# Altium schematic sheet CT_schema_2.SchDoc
size 309 x 321 mm
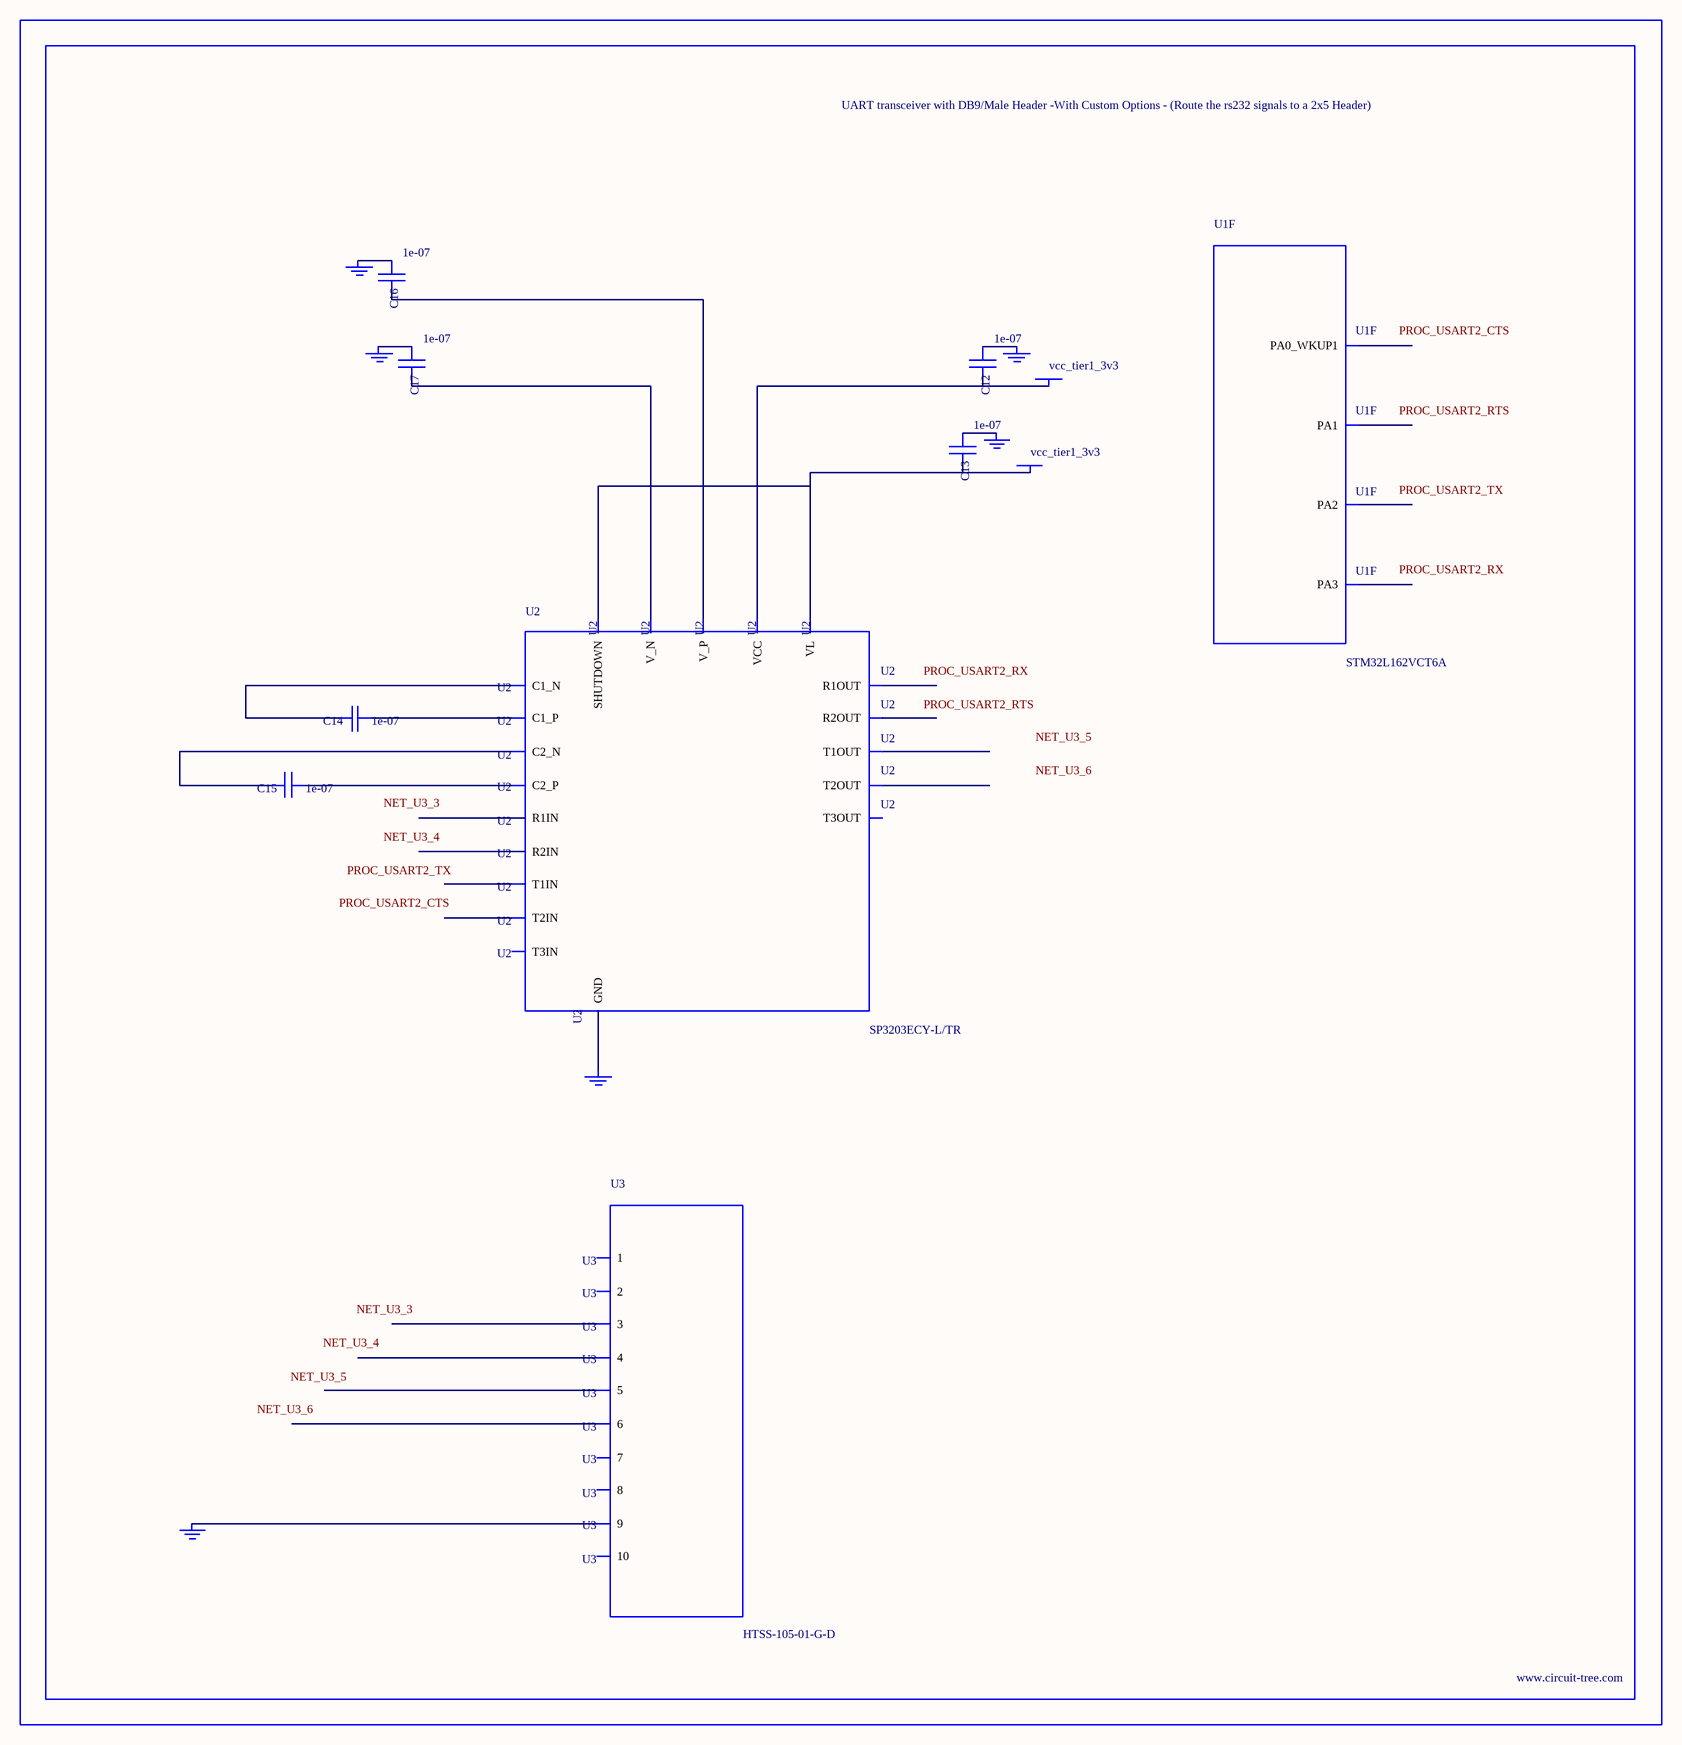
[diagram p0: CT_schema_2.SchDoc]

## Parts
BORDER1  (no value)
C12  1e-07  [C0402]
C13  1e-07  [C0402]
C14  1e-07  [C0402]
C15  1e-07  [C0402]
C16  1e-07  [C0402]
C17  1e-07  [C0402]
GND_INSTANCE_1_0  (no value)
GND_INSTANCE_1_1  (no value)
GND_INSTANCE_1_2  (no value)
GND_INSTANCE_1_3  (no value)
GND_INSTANCE_1_4  (no value)
GND_INSTANCE_1_5  (no value)
POWER_INSTANCE_1_0  vcc_tier1_3v3
POWER_INSTANCE_1_1  vcc_tier1_3v3
U1  STM32L162VCT6A  [LQFP100]  (part F of 9)
U2  SP3203ECY-L/TR  [TSSOP20-I]
U3  HTSS-105-01-G-D  [HTSS-105-01-G-D]

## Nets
NetC12_1: C12.1 GND_INSTANCE_1_3.0(GND)
NetC12_2: C12.2 POWER_INSTANCE_1_1.0(PWR) U2.19(VCC)
NetC13_1: C13.1 GND_INSTANCE_1_2.0(GND)
NetC13_2: C13.2 POWER_INSTANCE_1_0.0(PWR) U2.12(VL) U2.20(SHUTDOWN)
NetC14_1: C14.1 U2.1(C1_P)
NetC14_2: C14.2 U2.3(C1_N)
NetC15_1: C15.1 U2.4(C2_P)
NetC15_2: C15.2 U2.5(C2_N)
NetC16_1: C16.1 GND_INSTANCE_1_0.0(GND)
NetC16_2: C16.2 U2.2(V_P)
NetC17_1: C17.1 GND_INSTANCE_1_1.0(GND)
NetC17_2: C17.2 U2.6(V_N)
NetGND_INSTANCE_1_4_0: GND_INSTANCE_1_4.0(GND) U2.18(GND)
NetGND_INSTANCE_1_5_0: GND_INSTANCE_1_5.0(GND) U3.9

Not connected (* = marked no-connect by the designer): U1 23(PA0_WKUP1) 24(PA1) 25(PA2) 26(PA3); U2 7(T1IN) 8(T2IN) 9(T3IN) 10(R2OUT) 11(R1OUT) 13(R2IN) 14(R1IN) 15(T3OUT) 16(T2OUT) 17(T1OUT); U3 1 2 3 4 5 6 7 8 10

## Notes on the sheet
- Labels drawn without touching a wire or pin: NET_U3_3, NET_U3_4, NET_U3_5, NET_U3_6, PROC_USART2_CTS, PROC_USART2_RTS, PROC_USART2_RX, PROC_USART2_TX

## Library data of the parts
BORDER1 = BORDER_PAGE1
C12-C17 = C0402C104K3RACTU
GND_INSTANCE_1_0-GND_INSTANCE_1_5 = GND
POWER_INSTANCE_1_0 POWER_INSTANCE_1_1 = PWR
